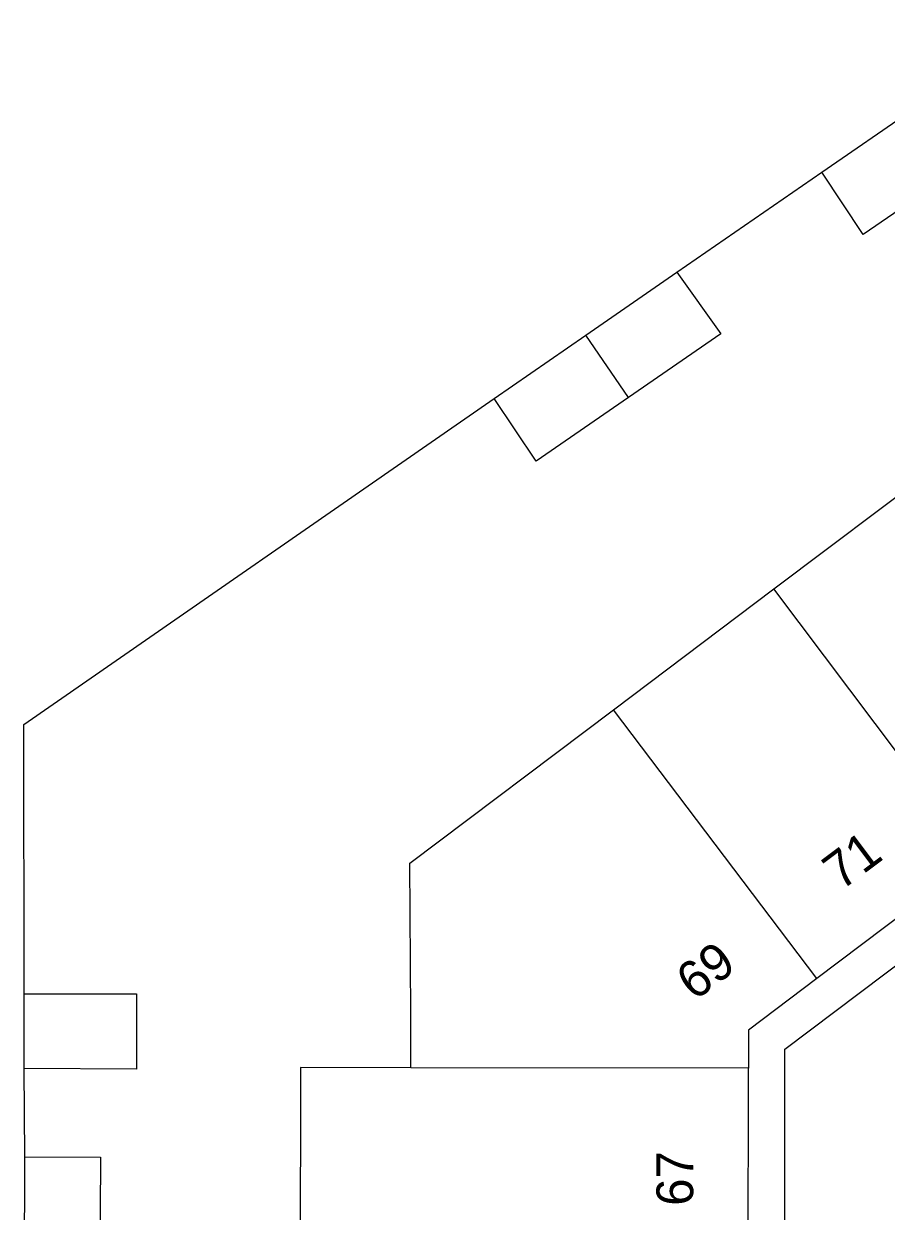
# Model space of a CAD drawing. Extents: x 160379 to 161131, y 383940 to 384849.
# Drawn here: x 160466.3 to 160489.76, y 384700.27 to 384732.55 of the extents above; entities that cross this region are included whole.
import ezdxf

# ---------------------------------------------------------------- set-up
doc = ezdxf.new("R2010")
doc.units = 0
for name, color, linetype in [('IMGEO_Erf', 7, 'Continuous'), ('IMGEO_Pand', 7, 'Continuous'), ('IMGEO_Pand_nummerreeks', 7, 'Continuous'), ('IMGEO_Voetpad_open', 7, 'Continuous')]:
    doc.layers.add(name, color=color, linetype=linetype)

msp = doc.modelspace()

# ---------------------------------------------------------------- linework, layer by layer
at = {"layer": 'IMGEO_Erf'}
for points in [[(160484.067, 384725.798), (160488.006, 384728.518)], [(160466.315, 384706.177), (160466.304, 384713.501), (160479.098, 384722.358)], [(160466.334, 384701.748), (160466.318, 384704.146)]]:
    msp.add_lwpolyline(points, dxfattribs=at)
at = {"layer": 'IMGEO_Pand'}
for points in [[(160488.006, 384728.518), (160490.479, 384730.219)], [(160491.634, 384728.533), (160489.129, 384726.818), (160488.006, 384728.518)], [(160481.586, 384724.08), (160484.067, 384725.798)], [(160484.067, 384725.798), (160485.262, 384724.12), (160482.751, 384722.39)], [(160479.098, 384722.358), (160481.586, 384724.08)], [(160482.751, 384722.39), (160481.586, 384724.08)], [(160482.751, 384722.39), (160480.239, 384720.66), (160479.098, 384722.358)], [(160486.706, 384717.186), (160491.047, 384720.451)], [(160482.338, 384713.899), (160486.706, 384717.186)], [(160492.216, 384709.865), (160486.706, 384717.186)], [(160476.827, 384704.172), (160476.827, 384705.657), (160476.8, 384709.734), (160482.338, 384713.899)], [(160487.876, 384706.598), (160482.338, 384713.899)], [(160492.216, 384709.865), (160487.876, 384706.598)], [(160487.876, 384706.598), (160486.012, 384705.196), (160486.012, 384704.16)], [(160466.315, 384706.177), (160469.372, 384706.18), (160469.375, 384704.132), (160466.318, 384704.146)], [(160466.318, 384704.146), (160466.315, 384706.177)], [(160476.827, 384704.172), (160473.83, 384704.176), (160473.823, 384698.766), (160476.827, 384698.765)], [(160486.012, 384704.16), (160476.827, 384704.172)], [(160486.009, 384698.761), (160486.012, 384704.16)], [(160466.325, 384698.714), (160466.334, 384701.748)], [(160466.334, 384701.748), (160468.387, 384701.741), (160468.377, 384698.707)]]:
    msp.add_lwpolyline(points, dxfattribs=at)
at = {"layer": 'IMGEO_Voetpad_open'}
msp.add_lwpolyline([(160524.356, 384632.684), (160487.022, 384676.465), (160487, 384704.676), (160523.198, 384731.929), (160524.022, 384732.549)], dxfattribs=at)

# ---------------------------------------------------------------- texts
at = {"layer": 'IMGEO_Pand_nummerreeks'}
for s, rotation, p in [('71', 36.9615, (160488.53, 384708.967)), ('69', 36.9615, (160484.546, 384705.97)), ('67', 89.9716, (160484.51, 384700.418))]:
    msp.add_text(s, height=1, rotation=rotation, dxfattribs=at).set_placement(p)

doc.saveas('drawing.dxf')
